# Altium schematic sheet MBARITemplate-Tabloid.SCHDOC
size Tabloid; Organization: Monterey Bay Aquarium Research Institute; Address1: 7700 Sandholdt Rd; Address2: Moss Landing, CA 95039-9644; CompanyName: MBARI
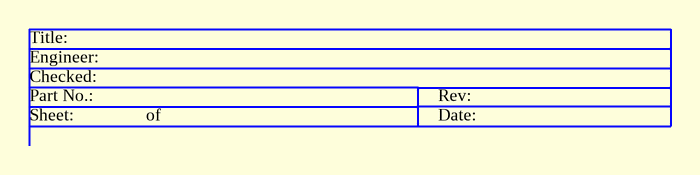
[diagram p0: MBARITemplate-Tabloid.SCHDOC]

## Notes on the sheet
- Sheet:
- Title:
- Engineer:
- Part No.:
- Checked:
- of
- Rev:
- Date:
